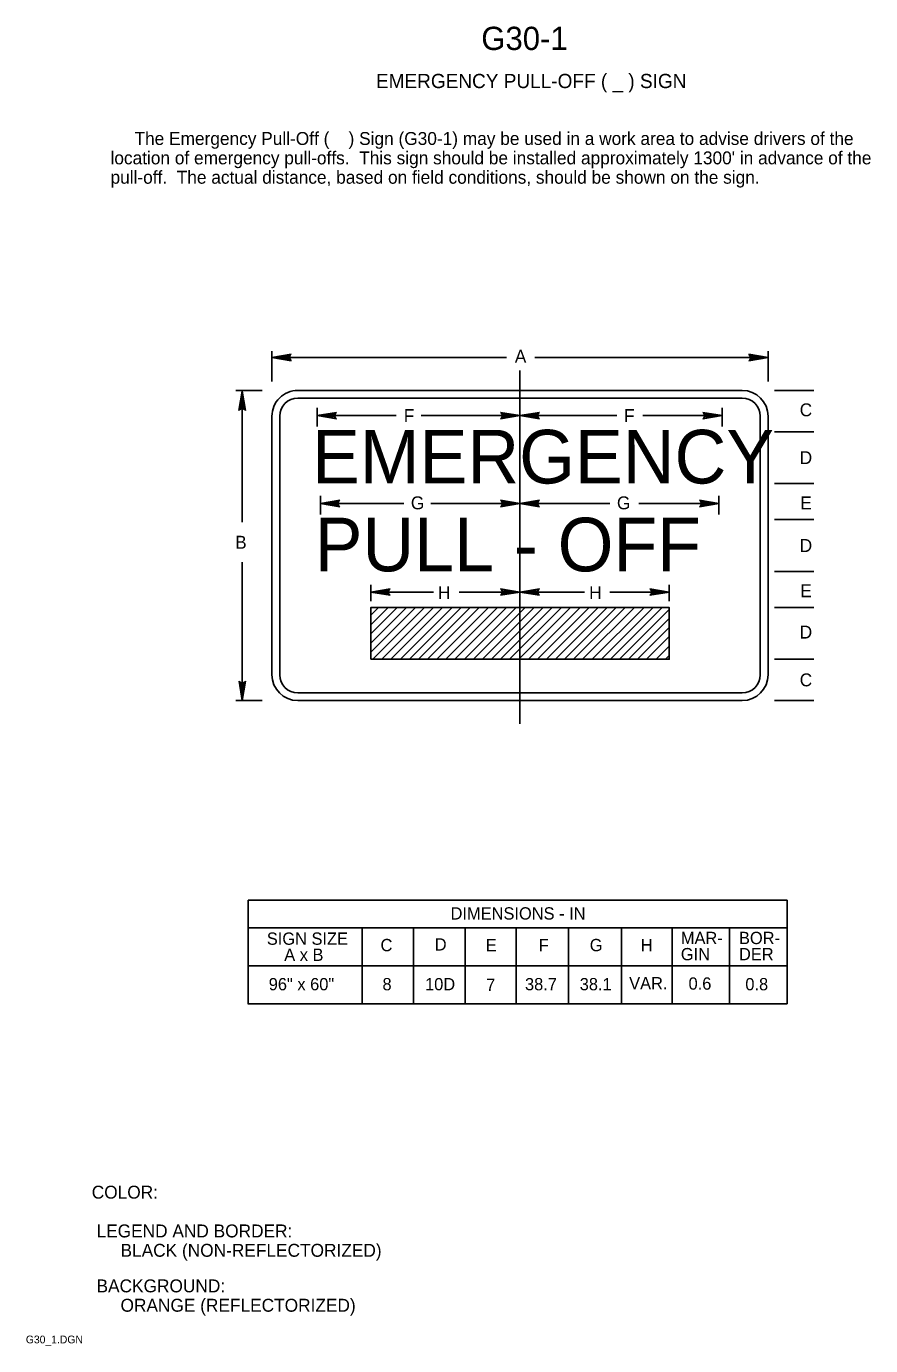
# Model space of a CAD drawing. Extents: x 0.013 to 0.176, y 0.004 to 0.259.
import ezdxf

# ---------------------------------------------------------------- set-up
doc = ezdxf.new("R2010")
doc.units = 0
doc.layers.add('1', color=7, linetype='Continuous')
doc.layers.add('3', color=7, linetype='Continuous')

# ---------------------------------------------------------------- blocks, each defined once
blk = doc.blocks.new('RARROW')
at = {"layer": '3'}
for p, q in [((-2.156, 0.285), (-2.2665, 0.384625)), ((-2.2665, 0.384625), (0, 0)), ((0, 0), (-2.2665, -0.379125)), ((-2.156, 0.285), (-2.075625, 0.12075)), ((0, 0), (-2.156, 0.285)), ((-2.14975, -0.2705), (0, 0)), ((-2.075625, 0.12075), (0, 0)), ((0, 0), (-2.074, -0.108)), ((-2.2665, -0.379125), (-2.14975, -0.2705)), ((-2.074, -0.108), (-2.14975, -0.2705))]:
    blk.add_line(p, q, dxfattribs=at)

msp = doc.modelspace()

# ---------------------------------------------------------------- linework, layer by layer
at = {"layer": '1'}
for p, q in [((0.10812, 0.12425), (0.10812, 0.19262)), ((0.06888, 0.18175), (0.06888, 0.18538)), ((0.14725, 0.18175), (0.14725, 0.18538)), ((0.0695, 0.16475), (0.0695, 0.16837)), ((0.14663, 0.16475), (0.14663, 0.16837)), ((0.07925, 0.148), (0.07925, 0.15113)), ((0.137, 0.148), (0.137, 0.15113)), ((0.07925, 0.14525), (0.08075, 0.14675)), ((0.07925, 0.14338), (0.08263, 0.14675)), ((0.07925, 0.14163), (0.08438, 0.14675)), ((0.07925, 0.13987), (0.08613, 0.14675)), ((0.07925, 0.13812), (0.08788, 0.14675)), ((0.07963, 0.13675), (0.08962, 0.14675)), ((0.08138, 0.13675), (0.09137, 0.14675)), ((0.08313, 0.13675), (0.09312, 0.14675)), ((0.085, 0.13675), (0.095, 0.14675)), ((0.08675, 0.13675), (0.09675, 0.14675)), ((0.0885, 0.13675), (0.0985, 0.14675)), ((0.09025, 0.13675), (0.10025, 0.14675)), ((0.092, 0.13675), (0.102, 0.14675)), ((0.09375, 0.13675), (0.10375, 0.14675)), ((0.0955, 0.13675), (0.1055, 0.14675)), ((0.09738, 0.13675), (0.10737, 0.14675)), ((0.09913, 0.13675), (0.10912, 0.14675)), ((0.10088, 0.13675), (0.11088, 0.14675)), ((0.10263, 0.13675), (0.11263, 0.14675)), ((0.10437, 0.13675), (0.11438, 0.14675)), ((0.10612, 0.13675), (0.11613, 0.14675)), ((0.10787, 0.13675), (0.11788, 0.14675)), ((0.10975, 0.13675), (0.11975, 0.14675)), ((0.1115, 0.13675), (0.1215, 0.14675)), ((0.11325, 0.13675), (0.12325, 0.14675)), ((0.115, 0.13675), (0.125, 0.14675)), ((0.11675, 0.13675), (0.12675, 0.14675)), ((0.1185, 0.13675), (0.1285, 0.14675)), ((0.12025, 0.13675), (0.13025, 0.14675)), ((0.12212, 0.13675), (0.13212, 0.14675)), ((0.12387, 0.13675), (0.13387, 0.14675)), ((0.12563, 0.13675), (0.13562, 0.14675)), ((0.12738, 0.13675), (0.137, 0.14638)), ((0.12912, 0.13675), (0.137, 0.14463)), ((0.13087, 0.13675), (0.137, 0.14288)), ((0.13262, 0.13675), (0.137, 0.14113)), ((0.1345, 0.13675), (0.137, 0.13925)), ((0.13625, 0.13675), (0.137, 0.1375))]:
    msp.add_line(p, q, dxfattribs=at)
msp.add_lwpolyline([(0.07925, 0.13675), (0.137, 0.13675), (0.137, 0.14675), (0.07925, 0.14675)], close=True, dxfattribs=at)
at = {"layer": '3'}
for p, q in [((0.06012, 0.1905), (0.06012, 0.19637)), ((0.1055, 0.19512), (0.06012, 0.19512)), ((0.111, 0.19512), (0.15613, 0.19512)), ((0.15613, 0.1905), (0.15613, 0.19637)), ((0.05825, 0.18875), (0.05312, 0.18875)), ((0.05437, 0.16325), (0.05437, 0.18875)), ((0.15113, 0.18875), (0.06512, 0.18875)), ((0.15113, 0.18725), (0.06512, 0.18725)), ((0.165, 0.18875), (0.15738, 0.18875)), ((0.08413, 0.18388), (0.06888, 0.18388)), ((0.10812, 0.18388), (0.089, 0.18388)), ((0.10812, 0.18388), (0.12688, 0.18388)), ((0.13187, 0.18388), (0.14725, 0.18388)), ((0.06012, 0.13375), (0.06012, 0.18375)), ((0.06162, 0.18375), (0.06162, 0.13375)), ((0.15463, 0.13375), (0.15463, 0.18375)), ((0.15613, 0.18375), (0.15613, 0.13375)), ((0.165, 0.18075), (0.15738, 0.18075)), ((0.165, 0.17075), (0.15738, 0.17075)), ((0.08563, 0.16687), (0.0695, 0.16687)), ((0.10812, 0.16687), (0.09087, 0.16687)), ((0.10812, 0.16687), (0.1255, 0.16687)), ((0.13112, 0.16687), (0.14663, 0.16687)), ((0.165, 0.16375), (0.15738, 0.16375)), ((0.05437, 0.1555), (0.05437, 0.12875)), ((0.165, 0.15375), (0.15738, 0.15375)), ((0.09137, 0.14975), (0.07925, 0.14975)), ((0.10812, 0.14975), (0.09638, 0.14975)), ((0.10812, 0.14975), (0.12062, 0.14975)), ((0.1255, 0.14975), (0.137, 0.14975)), ((0.165, 0.14675), (0.15738, 0.14675)), ((0.165, 0.13675), (0.15738, 0.13675)), ((0.06512, 0.13025), (0.15113, 0.13025)), ((0.05825, 0.12875), (0.05312, 0.12875)), ((0.15113, 0.12875), (0.06512, 0.12875)), ((0.165, 0.12875), (0.15738, 0.12875)), ((0.0555, 0.09014), (0.1598, 0.09014)), ((0.0555, 0.09012), (0.0555, 0.07)), ((0.1598, 0.09014), (0.1598, 0.07006)), ((0.1598, 0.08476), (0.0555, 0.08476)), ((0.07755, 0.08476), (0.07755, 0.07006)), ((0.0875, 0.08475), (0.0875, 0.07)), ((0.0975, 0.08475), (0.0975, 0.07)), ((0.10737, 0.08475), (0.10737, 0.07)), ((0.1175, 0.08475), (0.1175, 0.07)), ((0.12775, 0.08475), (0.12775, 0.07)), ((0.13755, 0.08476), (0.13755, 0.07006)), ((0.13755, 0.08476), (0.13755, 0.07113)), ((0.14867, 0.08476), (0.14867, 0.07006)), ((0.1598, 0.07741), (0.0555, 0.07741)), ((0.1598, 0.07006), (0.0555, 0.07006))]:
    msp.add_line(p, q, dxfattribs=at)
for centre, radius, start, end in [((0.06512, 0.18375), 0.005, 89.9453, 179.9453), ((0.06512, 0.18375), 0.0035, 90, 180), ((0.15113, 0.18375), 0.005, 0, 90), ((0.15113, 0.18375), 0.0035, 0, 90), ((0.06512, 0.13375), 0.005, 180, 270), ((0.06512, 0.13375), 0.0035, 180, 270), ((0.15113, 0.13375), 0.005, 270, 0), ((0.15113, 0.13375), 0.0035, 270, 0)]:
    msp.add_arc(centre, radius, start, end, dxfattribs=at)

# ---------------------------------------------------------------- block references
at = {"layer": '3', "xscale": 0.0016545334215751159}
for p, yscale, rotation in [((0.06012, 0.19512), 0.0016366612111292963, 180), ((0.05437, 0.18863), 0.0016366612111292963, 90), ((0.06888, 0.18388), 0.0016366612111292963, 180), ((0.10812, 0.18388), -0.0016366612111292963, 180), ((0.0695, 0.16687), 0.0016366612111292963, 180), ((0.10812, 0.16687), -0.0016366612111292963, 180), ((0.07925, 0.14975), 0.0016366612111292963, 180), ((0.10812, 0.14975), -0.0016366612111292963, 180), ((0.05437, 0.12875), 0.0016366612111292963, -90)]:
    msp.add_blockref('RARROW', p, dxfattribs=dict(at, yscale=yscale, rotation=rotation))
for p, yscale in [((0.15613, 0.19512), 0.0016366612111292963), ((0.10812, 0.18388), 0.0016366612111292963), ((0.14725, 0.18388), -0.0016366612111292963), ((0.10812, 0.16687), 0.0016366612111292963), ((0.14663, 0.16687), -0.0016366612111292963), ((0.10812, 0.14975), 0.0016366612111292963), ((0.137, 0.14975), -0.0016366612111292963)]:
    msp.add_blockref('RARROW', p, dxfattribs=dict(at, yscale=yscale))

# ---------------------------------------------------------------- texts
at = {"layer": '1'}
for s, height, p in [('G30-1', 0.0045, (0.10063, 0.25462)), ('EMERGENCY PULL-OFF ( _ ) SIGN', 0.0027503, (0.08025, 0.24725)), ('     The Emergency Pull-Off (    ) Sign (G30-1) may be used in a work area to advise drivers of the ', 0.0024998, (0.02888, 0.23625)), ("location of emergency pull-offs.  This sign should be installed approximately 1300' in advance of the ", 0.00249975, (0.02888, 0.2325)), ('pull-off.  The actual distance, based on field conditions, should be shown on the sign.', 0.0024998, (0.02888, 0.22875)), ('EMERGENCY', 0.010375, (0.06788, 0.17075)), ('PULL - OFF', 0.010375, (0.06838, 0.15375)), ('COLOR:', 0.0025, (0.02525, 0.03238)), (' LEGEND AND BORDER:', 0.0024998, (0.02525, 0.02488)), ('      BLACK (NON-REFLECTORIZED)', 0.0024998, (0.02525, 0.02113)), (' BACKGROUND:', 0.0024998, (0.02525, 0.01425)), ('      ORANGE (REFLECTORIZED)', 0.0024998, (0.02525, 0.0105)), ('G30_1.DGN', 0.0015, (0.0125, 0.00438))]:
    msp.add_text(s, height=height, dxfattribs=at).set_placement(p)
at = {"layer": '3'}
for s, height, p in [('A', 0.0025, (0.10712, 0.19412)), ('F', 0.0025, (0.08563, 0.18263)), ('F', 0.0025, (0.12825, 0.18263)), ('C', 0.0025, (0.16225, 0.18375)), ('D', 0.0025, (0.16225, 0.1745)), ('G', 0.0025, (0.087, 0.16575)), ('G', 0.0025, (0.12688, 0.16575)), ('E', 0.0025, (0.16237, 0.16575)), ('B', 0.0025, (0.053, 0.15813)), ('D', 0.0025, (0.16225, 0.1575)), ('H', 0.0025, (0.09225, 0.14838)), ('H', 0.0025, (0.1215, 0.14838)), ('E', 0.0025, (0.16237, 0.14875)), ('D', 0.0025, (0.16225, 0.14075)), ('C', 0.0025, (0.16225, 0.1315)), ('DIMENSIONS - IN', 0.0023752, (0.09469, 0.08638)), ('SIGN SIZE', 0.002375, (0.05913, 0.0815)), ('C', 0.00238, (0.08113, 0.08025)), ('D', 0.00238, (0.09162, 0.08038)), ('E', 0.00238, (0.1015, 0.08025)), ('F', 0.00238, (0.11175, 0.08025)), ('G', 0.00238, (0.12162, 0.08025)), ('H', 0.00238, (0.1315, 0.08025)), ('MAR-', 0.002375, (0.13925, 0.08163)), ('BOR-', 0.002375, (0.1505, 0.08163)), ('A x B', 0.002375, (0.0625, 0.07838)), ('GIN', 0.002375, (0.13925, 0.0785)), ('DER', 0.002375, (0.1505, 0.0785)), ('96" x 60"', 0.002375, (0.0595, 0.07269)), ('8', 0.00238, (0.08151, 0.07269)), ('10D', 0.002375, (0.08975, 0.07269)), ('7', 0.00238, (0.10156, 0.07256)), ('38.7', 0.002375, (0.10909, 0.07269)), ('38.1', 0.002375, (0.11968, 0.07269)), ('VAR.', 0.002375, (0.12925, 0.07287)), ('0.6', 0.002375, (0.14074, 0.07281)), ('0.8', 0.002375, (0.15173, 0.07269))]:
    msp.add_text(s, height=height, dxfattribs=at).set_placement(p)

doc.saveas('drawing.dxf')
